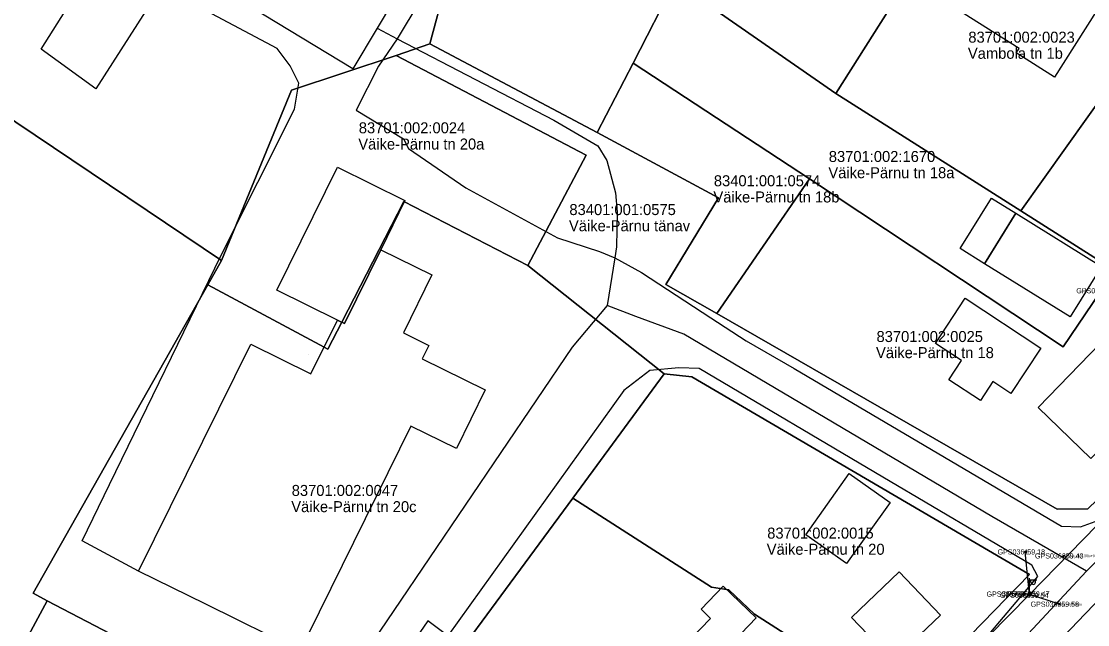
# Model space of a CAD drawing. Extents: x 580119 to 583377, y 6518915 to 6520820.
# Drawn here: x 581801.1 to 581946.3, y 6519827.6 to 6519909.9 of the extents above; entities that cross this region are included whole.
import ezdxf

# ---------------------------------------------------------------- set-up
doc = ezdxf.new("R2010")
doc.units = 0
for name, color, linetype in [('Hoone Elu- või ühiskondlik hoone', 7, 'Continuous'), ('Hoone Kõrval- või tootmishoone', 7, 'Continuous'), ('Kõrgrajatis Korsten', 7, 'Continuous'), ('L_AADRESS', 7, 'Continuous'), ('MAAMUDEL', 7, 'Continuous'), ('MOOTKORG-EH2000', 7, 'Continuous'), ('MOOTMPUNKT', 7, 'Continuous'), ('MOOTNR', 7, 'Continuous'), ('MPOHULIIN', 7, 'Continuous'), ('PIIR', 7, 'Continuous'), ('POST', 7, 'Continuous'), ('Rippe kõrgus', 7, 'Continuous'), ('Tee Liiklusala', 7, 'Continuous'), ('Tee Rada Püsikate', 7, 'Continuous'), ('Tee Tänav Püsikate', 7, 'Continuous'), ('TUNNUS', 7, 'Continuous')]:
    doc.layers.add(name, color=color, linetype=linetype)

msp = doc.modelspace()

# ---------------------------------------------------------------- linework, layer by layer
at = {"layer": 'Hoone Elu- või ühiskondlik hoone'}
for points in [[(581926.17, 6519913.04), (581932.01, 6519922.25), (581943.01, 6519915.28), (581943.98, 6519916.81), (581948.99, 6519913.64), (581941.79, 6519902.28), (581936.59, 6519905.58), (581936.98, 6519906.19)], [(581948.22, 6519876.46), (581943.94, 6519869.57), (581932.26, 6519876.82), (581936.54, 6519883.7)], [(581856.98, 6519875.29), (581853.1, 6519867.4), (581856.55, 6519865.69), (581855.65, 6519863.86), (581864.26, 6519859.61), (581860.32, 6519851.62), (581854.13, 6519854.68), (581840.08, 6519826.17), (581839.03, 6519824.04), (581826.18, 6519830.38), (581817.04, 6519834.89), (581832.3, 6519865.86), (581840.5, 6519861.81), (581844.12, 6519869.15), (581845.06, 6519868.68), (581850.01, 6519878.72)], [(581958.03, 6519861.95), (581946.74, 6519850.28), (581939.59, 6519857.22), (581950.87, 6519868.88)], [(581926.26, 6519828.92), (581919.8, 6519822.72), (581914.17, 6519828.6), (581920.63, 6519834.8)]]:
    msp.add_lwpolyline(points, close=True, dxfattribs=at)
at = {"layer": 'Hoone Kõrval- või tootmishoone'}
for points in [[(581850.01, 6519878.72), (581845.06, 6519868.68), (581844.12, 6519869.15), (581835.86, 6519873.21), (581844.13, 6519889.98), (581853.32, 6519885.45)], [(581936.54, 6519883.7), (581932.26, 6519876.82), (581928.95, 6519878.88), (581933.23, 6519885.76)], [(581939.96, 6519865.33), (581935.88, 6519859.14), (581933.42, 6519860.76), (581931.71, 6519858.16), (581927.41, 6519861), (581929.14, 6519863.63), (581925.6, 6519865.97), (581929.65, 6519872.12)], [(581919.4, 6519844.27), (581913.45, 6519835.93), (581907.91, 6519839.87), (581913.85, 6519848.22)], [(581901.18, 6519828.53), (581894.04, 6519821.07), (581890.8, 6519824.16), (581894.94, 6519828.47), (581893.66, 6519829.7), (581896.66, 6519832.85)]]:
    msp.add_lwpolyline(points, close=True, dxfattribs=at)
at = {"layer": 'Kõrgrajatis Korsten'}
msp.add_line((581840.18, 6519864.44), (581840.18, 6519864.44), dxfattribs=at)
at = {"layer": 'MOOTMPUNKT'}
for centre in [(581937.83, 6519837.53), (581943.07, 6519836.98), (581936.47, 6519831.78), (581938.3, 6519831.61), (581938.46, 6519831.8), (581942.47, 6519830.4)]:
    msp.add_circle(centre, 0.1, dxfattribs=at)
at = {"layer": 'MPOHULIIN'}
for p, q in [((581938.38, 6519831.71), (581937.83, 6519837.53)), ((581938.38, 6519831.71), (581936.47, 6519831.78)), ((581942.47, 6519830.4), (581938.38, 6519831.71))]:
    msp.add_line(p, q, dxfattribs=at)
msp.add_lwpolyline([(581859.1, 6519746.43), (581883.65, 6519775.9), (581910.63, 6519803.45), (581938.38, 6519831.71), (581969.55, 6519863.69), (582004.1, 6519898.63), (582043.97, 6519939.12), (582079.7, 6519981.43), (582116.09, 6520024.19), (582121.9, 6520051.43)], dxfattribs=at)
at = {"layer": 'PIIR'}
for points in [[(581793.83, 6519972.03), (581825.66, 6519952.76), (581826.05, 6519953.3), (581857.43, 6519934.09), (581863.13, 6519930.6), (581856.71, 6519906.79), (581852.12, 6519905.22), (581837.88, 6519900.5), (581828.31, 6519877.26), (581797.75, 6519897.83), (581797.87, 6519898.15), (581765.99, 6519918.16)], [(581863.13, 6519930.6), (581857.43, 6519934.09), (581859.27, 6519937.79), (581873.9, 6519965.21), (581905.78, 6519945.99), (581890.08, 6519915.3), (581884.43, 6519904.17), (581879.52, 6519894.73), (581856.71, 6519906.79)], [(581905.78, 6519945.99), (581931.29, 6519930.51), (581912, 6519900.05), (581890.08, 6519915.3)], [(581931.29, 6519930.51), (581958.54, 6519913.98), (581937.23, 6519884.02), (581912, 6519900.05)], [(581890.08, 6519915.3), (581912, 6519900.05), (581937.23, 6519884.02), (581950.04, 6519875.88), (581942.99, 6519865.51), (581908.42, 6519888.38), (581884.43, 6519904.17)], [(581958.54, 6519913.98), (581994.57, 6519891.85), (581968.11, 6519864.42), (581950.04, 6519875.88), (581937.23, 6519884.02)], [(581826.46, 6519873.97), (581828.31, 6519877.26), (581837.88, 6519900.5), (581852.12, 6519905.22), (581877.99, 6519891.65), (581870.06, 6519876.59), (581853.18, 6519885.33), (581844.72, 6519868.84), (581842.83, 6519865.16), (581841.71, 6519865.75)], [(581895.82, 6519870.02), (581888.86, 6519874.01), (581896.02, 6519885.82), (581879.52, 6519894.73), (581884.43, 6519904.17), (581908.42, 6519888.38)], [(581788.34, 6519879.84), (581797.75, 6519897.83), (581828.31, 6519877.26), (581826.46, 6519873.97), (581802.65, 6519831.88), (581804.59, 6519830.86), (581782.73, 6519790.33), (581751.53, 6519809.56)], [(581908.42, 6519888.38), (581942.99, 6519865.51), (581950.04, 6519875.88), (581968.11, 6519864.42), (581946.33, 6519843.38), (581942.19, 6519843.34), (581895.82, 6519870.02)], [(581826.46, 6519873.97), (581841.71, 6519865.75), (581842.83, 6519865.16), (581844.72, 6519868.84), (581853.18, 6519885.33), (581870.06, 6519876.59), (581888.65, 6519861.81), (581876.19, 6519844.87), (581860.51, 6519823.58), (581852.28, 6519812.4), (581846.31, 6519804.4), (581836.4, 6519809.77), (581838.04, 6519813.4), (581804.59, 6519830.86), (581802.65, 6519831.88)], [(581888.65, 6519861.81), (581892.4, 6519861.4), (581938.38, 6519834.43), (581920.78, 6519816.29), (581900.94, 6519829.02), (581897.43, 6519832.37), (581895.07, 6519832.71), (581876.19, 6519844.87)], [(581878.19, 6519814.14), (581875.63, 6519816.01), (581874.6, 6519814.57), (581861.96, 6519822.96), (581860.51, 6519823.58), (581876.19, 6519844.87), (581895.07, 6519832.71), (581897.43, 6519832.37), (581900.94, 6519829.02), (581920.78, 6519816.29), (581901.19, 6519796.81), (581877.65, 6519813.18)], [(581804.59, 6519830.86), (581838.04, 6519813.4), (581836.4, 6519809.77), (581814.17, 6519771.63), (581782.73, 6519790.33)]]:
    msp.add_lwpolyline(points, close=True, dxfattribs=at)
msp.add_lwpolyline([(581920.78, 6519816.29), (581938.38, 6519834.43), (581892.4, 6519861.4), (581888.65, 6519861.81), (581870.06, 6519876.59), (581877.99, 6519891.65), (581852.12, 6519905.22), (581856.71, 6519906.79), (581879.52, 6519894.73), (581896.02, 6519885.82), (581888.86, 6519874.01), (581895.82, 6519870.02), (581942.19, 6519843.34), (581946.33, 6519843.38)], dxfattribs=at)
at = {"layer": 'POST'}
for p, q in [((581938.38, 6519831.96), (581938.38, 6519833.96)), ((581938.38, 6519833.71), (581939.38, 6519833.71)), ((581938.6, 6519833.39), (581938.6, 6519833.71)), ((581939.22, 6519833.39), (581939.22, 6519833.71)), ((581938.38, 6519831.71), (581938.38, 6519831.71))]:
    msp.add_line(p, q, dxfattribs=at)
msp.add_circle((581938.38, 6519831.71), 0.25, dxfattribs=at)
msp.add_arc((581938.91, 6519833.39), 0.306, 180, 0, dxfattribs=at)
at = {"layer": 'Tee Liiklusala'}
for points in [[(582127.44, 6519951.92), (582116.27, 6519951.94), (582112.21, 6519951.93), (582101.55, 6519951.92), (582088.85, 6519952.43), (582079.08, 6519951.36), (582071.58, 6519948.62), (582061.42, 6519942.77), (582052.62, 6519934.65), (582052.02, 6519934.11), (582039.05, 6519922.65), (582015.05, 6519898.5), (581998.34, 6519881.78), (581964.06, 6519847.77), (581945.92, 6519829.05), (581913.09, 6519794.59)], [(581839.03, 6519824.04), (581826.18, 6519830.38), (581817.04, 6519834.89), (581809.33, 6519839.02), (581813.06, 6519846.73), (581828.27, 6519877.99), (581838.26, 6519897.92), (581838.85, 6519901.47), (581837.67, 6519903.83), (581835.9, 6519906.19), (581823.35, 6519912.9), (581820.99, 6519912.53), (581818, 6519911.29), (581811.22, 6519900.66), (581803.77, 6519906.09), (581812.48, 6519919.95), (581785.21, 6519937.48)], [(581858.29, 6519917.59), (581852.27, 6519907.51), (581849.72, 6519903.75), (581846.69, 6519897.75), (581853.13, 6519893.86), (581853.79, 6519892.54), (581861.59, 6519887.16), (581874.11, 6519880.35), (581879.83, 6519878.49), (581881.92, 6519877.65), (581885.53, 6519875.64), (581894.98, 6519869.46), (581899.78, 6519866.32), (581906.32, 6519862.54), (581942.78, 6519841.06), (581945.33, 6519840.94), (581947.36, 6519841.67)], [(581931.92, 6519825.13), (581939.52, 6519834.18), (581938.73, 6519835.71), (581918.41, 6519847.74), (581893.41, 6519862.54), (581890.63, 6519862.61), (581886.7, 6519862.26), (581883.12, 6519859.54), (581859.16, 6519826.1), (581856.45, 6519828.14), (581848.87, 6519817.07)]]:
    msp.add_lwpolyline(points, dxfattribs=at)
at = {"layer": 'Tee Rada Püsikate'}
msp.add_lwpolyline([(581849.52, 6519908.96), (581852.27, 6519907.51), (581873.6, 6519896.42), (581879.6, 6519892.88), (581880.81, 6519890.9), (581881.99, 6519886.51), (581882.24, 6519883.87), (581882.13, 6519879.15), (581881.92, 6519877.65), (581880.88, 6519871.13)], dxfattribs=at)
at = {"layer": 'Tee Tänav Püsikate'}
for points in [[(581784.93, 6519964.78), (581787.12, 6519963.47), (581853.62, 6519923.72), (581855.53, 6519921.6), (581855.53, 6519919.04), (581849.52, 6519908.96)], [(581849.52, 6519908.96), (581846.2, 6519903.41), (581775.42, 6519946.31)], [(581946.17, 6519834.9), (581969.4, 6519858.35), (582003.51, 6519892.41)], [(581880.88, 6519871.13), (581876.11, 6519865.43), (581846.95, 6519822.37)], [(581946.17, 6519834.9), (581933.25, 6519842.36), (581891.31, 6519867.22), (581884.76, 6519869.65), (581880.88, 6519871.13)], [(581893.77, 6519774.39), (581901.27, 6519785.85), (581907.2, 6519792.99), (581946.17, 6519834.9)]]:
    msp.add_lwpolyline(points, dxfattribs=at)

# ---------------------------------------------------------------- texts
at = {"layer": 'L_AADRESS'}
for s, p in [('Vambola tn 1b', (581930.01, 6519904.77)), ('Väike-Pärnu tn 20a', (581846.96, 6519892.4)), ('Väike-Pärnu tn 18a', (581911, 6519888.49)), ('Väike-Pärnu tn 18b', (581895.34, 6519885.18)), ('Väike-Pärnu tänav', (581875.66, 6519881.25)), ('Väike-Pärnu tn 18', (581917.49, 6519863.95)), ('Väike-Pärnu tn 20c', (581837.83, 6519842.95)), ('Väike-Pärnu tn 20', (581902.6, 6519837.14))]:
    msp.add_text(s, height=1.5, dxfattribs=at).set_placement(p)
at = {"layer": 'MAAMUDEL'}
for s, p in [(' tv', (581937.83, 6519837.36)), (' mp_ohl6.95m', (581942.47, 6519830.22))]:
    msp.add_text(s, height=0.35, dxfattribs=at).set_placement(p)
at = {"layer": 'MOOTKORG-EH2000'}
for s, p in [(' 59.18', (581937.83, 6519837.18)), (' 59.43', (581943.07, 6519836.63)), (' 59.30', (581936.47, 6519831.43)), (' 59.54', (581938.3, 6519831.26)), (' 59.47', (581938.46, 6519831.45)), (' 59.58', (581942.47, 6519830.05))]:
    msp.add_text(s, height=0.7, dxfattribs=at).set_placement(p)
at = {"layer": 'MOOTNR'}
for s, p in [('GPS0364 ', (581944.78, 6519872.79)), ('GPS0361 ', (581934.05, 6519837.18)), ('GPS0362 ', (581939.15, 6519836.63)), ('GPS0357 ', (581932.55, 6519831.43)), ('GPS0358 ', (581934.38, 6519831.26)), ('GPS0359 ', (581934.54, 6519831.45)), ('GPS0360 ', (581938.55, 6519830.05))]:
    msp.add_text(s, height=0.7, dxfattribs=at).set_placement(p)
at = {"layer": 'Rippe kõrgus'}
msp.add_text(' el_mp_ohl7.30tv+0.30mp', height=0.35, dxfattribs=at).set_placement((581943.07, 6519836.81))
at = {"layer": 'TUNNUS'}
for s, p in [('83701:002:0023', (581930.07, 6519906.97)), ('83701:002:0024', (581847.03, 6519894.61)), ('83701:002:1670', (581911.06, 6519890.7)), ('83401:001:0574', (581895.4, 6519887.39)), ('83401:001:0575', (581875.72, 6519883.46)), ('83701:002:0025', (581917.56, 6519866.15)), ('83701:002:0047', (581837.89, 6519845.16)), ('83701:002:0015', (581902.67, 6519839.34))]:
    msp.add_text(s, height=1.5, dxfattribs=at).set_placement(p)

doc.saveas('drawing.dxf')
